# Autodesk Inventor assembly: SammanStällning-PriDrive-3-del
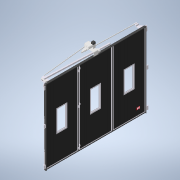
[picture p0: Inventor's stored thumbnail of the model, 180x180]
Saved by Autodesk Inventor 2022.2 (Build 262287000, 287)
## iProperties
Created: 2022-02
Part Number: SammanStällning-PriDrive-3-del
Document SubType Name: Assembly
Designer: cl
Author: cl
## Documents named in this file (22)
- G:\AutoCad\Carl Lund\3D-modeller systemlösningar\3D-modell-systemlösning-2022\SammanStällning-PriDrive-3-del.iam
- G:\AutoCad\Carl Lund\3D-modeller systemlösningar\3D-modell-systemlösning-2022\Parts\BladKomplett2022.iam
- G:\AutoCad\Carl Lund\3D-modeller systemlösningar\3D-modell-systemlösning-2022\Parts\MellanGångjärnH.ipt
- G:\AutoCad\Carl Lund\3D-modeller systemlösningar\3D-modell-systemlösning-2022\Parts\MellanGångjärnV.ipt
- G:\AutoCad\Carl Lund\3D-modeller systemlösningar\3D-modell-systemlösning-2022\Parts\Karmstyrning.ipt
- G:\AutoCad\Carl Lund\3D-modeller systemlösningar\3D-modell-systemlösning-2022\Parts\SidotätningUppe.ipt
- G:\AutoCad\Carl Lund\3D-modeller systemlösningar\3D-modell-systemlösning-2022\Parts\SidoTätning.ipt
- G:\AutoCad\Carl Lund\3D-modeller systemlösningar\3D-modell-systemlösning-2022\Parts\SläpList.ipt
- G:\AutoCad\Carl Lund\3D-modeller systemlösningar\3D-modell-systemlösning-2022\Parts\GummilistMellan.ipt
- G:\AutoCad\Carl Lund\3D-modeller systemlösningar\3D-modell-systemlösning-2022\Styrande.iam
- G:\AutoCad\Carl Lund\3D-modeller systemlösningar\3D-modell-systemlösning-2022\Parts\PriDrive\Karmgångjärn-PriDrive.ipt
- G:\AutoCad\Carl Lund\3D-modeller systemlösningar\3D-modell-systemlösning-2022\Parts\PriDrive\VinkeljärnStyrskena2.ipt
- G:\AutoCad\Carl Lund\3D-modeller systemlösningar\3D-modell-systemlösning-2022\Parts\PriDrive\VinkeljärnStyrskena.ipt
- G:\AutoCad\Carl Lund\3D-modeller systemlösningar\3D-modell-systemlösning-2022\Parts\StyrrulleH.ipt
- G:\AutoCad\Carl Lund\3D-modeller systemlösningar\3D-modell-systemlösning-2022\Parts\MotorKåpa.ipt
- G:\AutoCad\Carl Lund\3D-modeller systemlösningar\3D-modell-systemlösning-2022\Parts\Motor.ipt
- G:\AutoCad\Carl Lund\3D-modeller systemlösningar\3D-modell-systemlösning-2022\Parts\Växellåda.ipt
- G:\AutoCad\Carl Lund\3D-modeller systemlösningar\3D-modell-systemlösning-2022\Parts\MotorPlatta-3del.ipt
- G:\AutoCad\Carl Lund\3D-modeller systemlösningar\3D-modell-systemlösning-2022\Parts\Länkarm2-3Del.ipt
- G:\AutoCad\Carl Lund\3D-modeller systemlösningar\3D-modell-systemlösning-2022\Parts\Länkarm-3Del.ipt
- G:\AutoCad\Carl Lund\3D-modeller systemlösningar\3D-modell-systemlösning-2022\Parts\Styrskena-PD.ipt
- G:\AutoCad\Carl Lund\3D-modeller systemlösningar\3D-modell-systemlösning-2022\Parts\Logga.ipt
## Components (43 placed, 20 different names)
1. Logga:1 — Mate:200, Mate:201, Mate:202
2. BladKomplett2022:1 [sub-assembly] — Mate:1, Mate:2, Flush:1, Flush:2, Flush:3, Flush:8, Flush:28, Flush:29, Mate:28, Flush:30, Mate:42, Mate:39, Mate:43, Flush:99, Flush:100, Flush:101, Flush:102, Flush:103, Flush:104, Flush:112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
3. BladKomplett2022:2 [sub-assembly] — Flush:2, Flush:3, Flush:8, Flush:106, Mate:52, Flush:107, Flush:118, Flush:121, Mate:65, Flush:148, Flush:149, Mate:185, Flush:182, Flush:183, Flush:197
4. BladKomplett2022:3 [sub-assembly] — Flush:30, Flush:101, Flush:102, Mate:53, Flush:114, Flush:115, Flush:180, Mate:198
5. BladKomplett2022:4 [sub-assembly] — Flush:32, Flush:100, Flush:103, Mate:54, Flush:122, Flush:123, Flush:128, Mate:64, Flush:146, Flush:147
6. BladKomplett2022:5 [sub-assembly] — Flush:31, Flush:99, Flush:104, Flush:129, Mate:55, Flush:130, Mate:63, Flush:144, Flush:145, Flush:189
7. BladKomplett2022:6 [sub-assembly] — Mate:28, Flush:28, Flush:29, Flush:31, Flush:32, Mate:38, Flush:131, Flush:134, Flush:137, Mate:56, Flush:138, Flush:139, Mate:58, Mate:59, Mate:62, Flush:142, Flush:143, Flush:152, Mate:69, Mate:70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
8. Karmstyrning:2 — Mate:38, Mate:56, Flush:138, Flush:141
9. Karmstyrning:3 — Mate:39, Mate:43, Flush:140
10. Karmstyrning:4 — Mate:42, Mate:60, Mate:61, Flush:141
11. Karmstyrning:1 — Flush:139, Mate:58, Mate:59, Flush:140
12. MellanGångjärnV:3 — Flush:110, Flush:111, Flush:113
13. MellanGångjärnV:2 — Flush:108, Flush:109, Flush:110, Flush:111, Flush:112
14. MellanGångjärnV:1 — Flush:106, Mate:52, Flush:107, Flush:108, Flush:109
15. MellanGångjärnH:2 — Flush:116, Flush:117, Flush:118, Flush:119, Flush:120
16. MellanGångjärnH:3 — Flush:119, Flush:120, Flush:121
17. MellanGångjärnH:1 — Mate:53, Flush:114, Flush:115, Flush:116, Flush:117
18. MellanGångjärnV:6 — Flush:124, Flush:125, Flush:126, Flush:127, Flush:128
19. MellanGångjärnV:5 — Flush:126, Flush:127, Flush:129
20. MellanGångjärnV:4 — Mate:54, Flush:122, Flush:123, Flush:124, Flush:125
21. MellanGångjärnH:5 — Flush:132, Flush:133, Flush:134
22. MellanGångjärnH:6 — Flush:135, Flush:136, Flush:137
23. MellanGångjärnH:4 — Mate:55, Flush:130, Flush:131, Flush:132, Flush:133, Flush:135, Flush:136
24. GummilistMellan:2 — Mate:63, Flush:144, Flush:145
25. GummilistMellan:3 — Mate:64, Flush:146, Flush:147
26. GummilistMellan:4 — Mate:65, Flush:148, Flush:149
27. GummilistMellan:5 — Mate:66, Flush:150, Flush:151
28. SidotätningUppe:1 — Mate:67, Mate:68, Flush:152, Mate:71, Mate:74
29. SidoTätning:1 — Mate:69, Mate:70, Mate:71, Mate:76
30. SidoTätning:2 — Mate:72, Mate:73, Mate:74
31. SläpList:1 — Mate:75, Flush:153, Mate:76
32. GummilistMellan:1 — Mate:62, Flush:142, Flush:143
33. Karmgångjärn-PriDrive:1 — Mate:177, Flush:176, Mate:178, Flush:179, Mate:188, Tangent:3, Tangent:4
34. VinkeljärnStyrskena2:1 — Flush:179, Flush:180, Mate:181, Mate:183, Flush:187
35. VinkeljärnStyrskena:2 — Mate:187, Flush:187, Mate:199
36. StyrrulleH:1 — Mate:185, Flush:182, Flush:183, Tangent:2
37. Styrskena-PD:1 — Mate:181, Mate:183, Tangent:2, Mate:187, Mate:198
38. Länkarm-3Del:1 — Flush:190, Tangent:3, Flush:191, Mate:197
39. Länkarm2-3Del:1 — Flush:191, Mate:196, Tangent:4
40. MotorKåpa:1 — Mate:195, Flush:195, Flush:196
41. Motor:1 — Mate:193, Flush:194, Mate:194, Mate:195, Flush:195, Flush:196
42. Växellåda:1 — Mate:192, Flush:192, Flush:193, Flush:194, Mate:194
43. MotorPlatta-3del:1 — Mate:188, Flush:189, Flush:190, Mate:192, Flush:192, Flush:193, Mate:193, Flush:197, Mate:196, Mate:197, Mate:199
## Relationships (130: Flush 78, Mate 49, Tangent 3)
- Mate:1: BladKomplett2022:1
- Mate:2: BladKomplett2022:1
- Flush:1: BladKomplett2022:1
- Flush:2: BladKomplett2022:1 ↔ BladKomplett2022:2
- Flush:3: BladKomplett2022:1 ↔ BladKomplett2022:2
- Flush:8: BladKomplett2022:1 ↔ BladKomplett2022:2
- Mate:28: BladKomplett2022:1 ↔ BladKomplett2022:6
- Flush:28: BladKomplett2022:1 ↔ BladKomplett2022:6
- Flush:29: BladKomplett2022:1 ↔ BladKomplett2022:6
- Flush:30: BladKomplett2022:1 ↔ BladKomplett2022:3
- Flush:31: BladKomplett2022:5 ↔ BladKomplett2022:6
- Flush:32: BladKomplett2022:4 ↔ BladKomplett2022:6
- Mate:38: BladKomplett2022:6 ↔ Karmstyrning:2
- Mate:39: BladKomplett2022:1 ↔ Karmstyrning:3
- Mate:42: BladKomplett2022:1 ↔ Karmstyrning:4
- Mate:43: BladKomplett2022:1 ↔ Karmstyrning:3
- Flush:99: BladKomplett2022:1 ↔ BladKomplett2022:5
- Flush:100: BladKomplett2022:1 ↔ BladKomplett2022:4
- Flush:101: BladKomplett2022:1 ↔ BladKomplett2022:3
- Flush:102: BladKomplett2022:1 ↔ BladKomplett2022:3
- Flush:103: BladKomplett2022:1 ↔ BladKomplett2022:4
- Flush:104: BladKomplett2022:1 ↔ BladKomplett2022:5
- Flush:106: BladKomplett2022:2 ↔ MellanGångjärnV:1
- Mate:52: BladKomplett2022:2 ↔ MellanGångjärnV:1
- Flush:107: BladKomplett2022:2 ↔ MellanGångjärnV:1
- Flush:108: MellanGångjärnV:2 ↔ MellanGångjärnV:1
- Flush:109: MellanGångjärnV:2 ↔ MellanGångjärnV:1
- Flush:110: MellanGångjärnV:3 ↔ MellanGångjärnV:2
- Flush:111: MellanGångjärnV:3 ↔ MellanGångjärnV:2
- Flush:112: BladKomplett2022:1 ↔ MellanGångjärnV:2
- Flush:113: BladKomplett2022:1 ↔ MellanGångjärnV:3
- Mate:53: BladKomplett2022:3 ↔ MellanGångjärnH:1
- Flush:114: BladKomplett2022:3 ↔ MellanGångjärnH:1
- Flush:115: BladKomplett2022:3 ↔ MellanGångjärnH:1
- Flush:116: MellanGångjärnH:2 ↔ MellanGångjärnH:1
- Flush:117: MellanGångjärnH:2 ↔ MellanGångjärnH:1
- Flush:118: BladKomplett2022:2 ↔ MellanGångjärnH:2
- Flush:119: MellanGångjärnH:2 ↔ MellanGångjärnH:3
- Flush:120: MellanGångjärnH:2 ↔ MellanGångjärnH:3
- Flush:121: BladKomplett2022:2 ↔ MellanGångjärnH:3
- Mate:54: BladKomplett2022:4 ↔ MellanGångjärnV:4
- Flush:122: BladKomplett2022:4 ↔ MellanGångjärnV:4
- Flush:123: BladKomplett2022:4 ↔ MellanGångjärnV:4
- Flush:124: MellanGångjärnV:6 ↔ MellanGångjärnV:4
- Flush:125: MellanGångjärnV:6 ↔ MellanGångjärnV:4
- Flush:126: MellanGångjärnV:6 ↔ MellanGångjärnV:5
- Flush:127: MellanGångjärnV:6 ↔ MellanGångjärnV:5
- Flush:128: BladKomplett2022:4 ↔ MellanGångjärnV:6
- Flush:129: BladKomplett2022:5 ↔ MellanGångjärnV:5
- Mate:55: BladKomplett2022:5 ↔ MellanGångjärnH:4
- Flush:130: BladKomplett2022:5 ↔ MellanGångjärnH:4
- Flush:131: BladKomplett2022:6 ↔ MellanGångjärnH:4
- Flush:132: MellanGångjärnH:5 ↔ MellanGångjärnH:4
- Flush:133: MellanGångjärnH:5 ↔ MellanGångjärnH:4
- Flush:134: BladKomplett2022:6 ↔ MellanGångjärnH:5
- Flush:135: MellanGångjärnH:6 ↔ MellanGångjärnH:4
- Flush:136: MellanGångjärnH:6 ↔ MellanGångjärnH:4
- Flush:137: BladKomplett2022:6 ↔ MellanGångjärnH:6
- Mate:56: BladKomplett2022:6 ↔ Karmstyrning:2
- Flush:138: BladKomplett2022:6 ↔ Karmstyrning:2
- Flush:139: BladKomplett2022:6 ↔ Karmstyrning:1
- Mate:58: BladKomplett2022:6 ↔ Karmstyrning:1
- Mate:59: BladKomplett2022:6 ↔ Karmstyrning:1
- Flush:140: Karmstyrning:3 ↔ Karmstyrning:1
- Mate:60: BladKomplett2022:1 ↔ Karmstyrning:4
- Mate:61: BladKomplett2022:1 ↔ Karmstyrning:4
- Flush:141: Karmstyrning:2 ↔ Karmstyrning:4
- Mate:62: BladKomplett2022:6 ↔ GummilistMellan:1
- Flush:142: BladKomplett2022:6 ↔ GummilistMellan:1
- Flush:143: BladKomplett2022:6 ↔ GummilistMellan:1
- Mate:63: BladKomplett2022:5 ↔ GummilistMellan:2
- Flush:144: BladKomplett2022:5 ↔ GummilistMellan:2
- Flush:145: BladKomplett2022:5 ↔ GummilistMellan:2
- Mate:64: BladKomplett2022:4 ↔ GummilistMellan:3
- Flush:146: BladKomplett2022:4 ↔ GummilistMellan:3
- Flush:147: BladKomplett2022:4 ↔ GummilistMellan:3
- Mate:65: BladKomplett2022:2 ↔ GummilistMellan:4
- Flush:148: BladKomplett2022:2 ↔ GummilistMellan:4
- Flush:149: BladKomplett2022:2 ↔ GummilistMellan:4
- Mate:66: BladKomplett2022:1 ↔ GummilistMellan:5
- Flush:150: BladKomplett2022:1 ↔ GummilistMellan:5
- Flush:151: BladKomplett2022:1 ↔ GummilistMellan:5
- Mate:67: BladKomplett2022:1 ↔ SidotätningUppe:1
- Mate:68: BladKomplett2022:1 ↔ SidotätningUppe:1
- Flush:152: BladKomplett2022:6 ↔ SidotätningUppe:1
- Mate:69: BladKomplett2022:6 ↔ SidoTätning:1
- Mate:70: BladKomplett2022:6 ↔ SidoTätning:1
- Mate:71: SidotätningUppe:1 ↔ SidoTätning:1
- Mate:72: BladKomplett2022:1 ↔ SidoTätning:2
- Mate:73: BladKomplett2022:1 ↔ SidoTätning:2
- Mate:74: SidotätningUppe:1 ↔ SidoTätning:2
- Mate:75: BladKomplett2022:1 ↔ SläpList:1
- Flush:153: BladKomplett2022:1 ↔ SläpList:1
- Mate:76: SidoTätning:1 ↔ SläpList:1
- Mate:177: BladKomplett2022:1 ↔ Karmgångjärn-PriDrive:1
- Flush:176: BladKomplett2022:1 ↔ Karmgångjärn-PriDrive:1
- Mate:178: BladKomplett2022:1 ↔ Karmgångjärn-PriDrive:1
- Flush:179: Karmgångjärn-PriDrive:1 ↔ VinkeljärnStyrskena2:1
- Flush:180: BladKomplett2022:3 ↔ VinkeljärnStyrskena2:1
- Mate:181: VinkeljärnStyrskena2:1 ↔ Styrskena-PD:1
- Mate:183: VinkeljärnStyrskena2:1 ↔ Styrskena-PD:1
- Mate:185: BladKomplett2022:2 ↔ StyrrulleH:1
- Flush:182: BladKomplett2022:2 ↔ StyrrulleH:1
- Flush:183: BladKomplett2022:2 ↔ StyrrulleH:1
- Tangent:2: StyrrulleH:1 ↔ Styrskena-PD:1
- Mate:187: VinkeljärnStyrskena:2 ↔ Styrskena-PD:1
- Flush:187: VinkeljärnStyrskena2:1 ↔ VinkeljärnStyrskena:2
- Mate:188: Karmgångjärn-PriDrive:1 ↔ MotorPlatta-3del:1
- Flush:189: BladKomplett2022:5 ↔ MotorPlatta-3del:1
- Flush:190: Länkarm-3Del:1 ↔ MotorPlatta-3del:1
- Tangent:3: Karmgångjärn-PriDrive:1 ↔ Länkarm-3Del:1
- Flush:191: Länkarm-3Del:1 ↔ Länkarm2-3Del:1
- Mate:192: Växellåda:1 ↔ MotorPlatta-3del:1
- Flush:192: Växellåda:1 ↔ MotorPlatta-3del:1
- Flush:193: Växellåda:1 ↔ MotorPlatta-3del:1
- Mate:193: Motor:1 ↔ MotorPlatta-3del:1
- Flush:194: Motor:1 ↔ Växellåda:1
- Mate:194: Motor:1 ↔ Växellåda:1
- Mate:195: MotorKåpa:1 ↔ Motor:1
- Flush:195: MotorKåpa:1 ↔ Motor:1
- Flush:196: MotorKåpa:1 ↔ Motor:1
- Flush:197: BladKomplett2022:2 ↔ MotorPlatta-3del:1
- Mate:196: Länkarm2-3Del:1 ↔ MotorPlatta-3del:1
- Tangent:4: Karmgångjärn-PriDrive:1 ↔ Länkarm2-3Del:1
- Mate:197: Länkarm-3Del:1 ↔ MotorPlatta-3del:1
- Mate:198: BladKomplett2022:3 ↔ Styrskena-PD:1
- Mate:199: VinkeljärnStyrskena:2 ↔ MotorPlatta-3del:1
- Mate:200: Logga:1 ↔ BladKomplett2022:6
- Mate:201: Logga:1 ↔ BladKomplett2022:6
- Mate:202: Logga:1 ↔ BladKomplett2022:6
## Named parameters: Blad2 = 1358.33333 mm, Blad3 = 0, Blad4 = 0, Blad5 = 0, MGJ12Djup = 0, MGJ12Bredd = 0, MGJ56Djup = 48 mm, MGJ23Djup = 48 mm, MGJ45Djup = 48 mm, GarageRegel5 = 0, GarageRegel6 = 0, BladBredd = 1333.33333 mm, Fönsterhöjd = 862 mm, Blad2_1 = 1358.33333 mm, Blad3_1 = 0, Blad4_1 = 0, Blad5_1 = 0, Blad6 = 2025 mm, MGJ12Djup_1 = 0, MGJ12Bredd_1 = 0, MGJ2Djup = 0, MGJ2Bredd = 5012.5 mm, MGJ56Djup_1 = 48 mm, MGJ23Djup_1 = 48 mm, MGJ45Djup_1 = 48 mm, GarageRegel5_1 = 0, GarageRegel6_1 = 0, StyrskenaV = 2766.66667 mm, Styrrulle2Djup = 48 mm, FönsterhöjdStyrning = 862 mm, FönsterKarm = 54 mm, AndraGlasraden = 0, BrösthöjdStyrning2 = 0.0001 mm, InfälldGångDörr = 0, Infälldstyr = 1012.5 mm, EnDelGångDörr = 0, VinkelJärnStyrSkena = 2666.66667 mm
